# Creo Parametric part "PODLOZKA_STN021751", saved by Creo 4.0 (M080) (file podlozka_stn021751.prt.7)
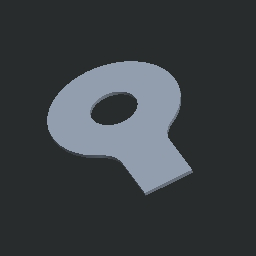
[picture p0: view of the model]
Units: Custom; MM, KILOGRAM, SECS
Materials in the file: OCEL_N

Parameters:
  MFG_WP_MATERIAL = "OCEL"
  NAZOV = "PODLOZKA_STN021751"
  NORMA = "STN 02 1751"
  PTC_MATERIAL_NAME = "OCEL_N"

Other parameters: HMOTNOST, HUSTOTA

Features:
  1. protrusion
  2. round
  3. cut
  4. cut
  5. round
  6. cut
  7. datum plane "DTM1"
  8. protrusion
  9. round

Layers: 1, 2, 3, 4, 5, 6, 7, 8, 9, 10, 11, 12, 13, 14, 15, 16, 17, 18, 19, 20, 21, 22, 23, 24, 25, 26, 27, 28, 29, 30, 31, 32

Family table entries: GENERIC, PODLOZKA_6_4, PODLOZKA_STN021751, value(d_val), 2/2, 2/2, value(i_val), PODLOZKA_8_4, PODLOZKA_STN021751, 2/6, 2/ , 2/4, PODLOZKA_10_5, PODLOZKA_STN021751, !/%, 2/:, 2/$, 2/6, PODLOZKA_13, PODLOZKA_STN021751, !/*, 2/>, 2/(, 2/<, 2/$, PODLOZKA_17, PODLOZKA_STN021751, !/1, 2/B, 2/., 2/@, 2/$, PODLOZKA_21, PODLOZKA_STN021751, !/5, 2/E, 2/2, 2/B, 2/$, PODLOZKA_25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

Surfaces: 5 plane, 4 cylinder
